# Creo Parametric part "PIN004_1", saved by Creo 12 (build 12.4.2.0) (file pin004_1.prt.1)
Units: Custom; MM, KILOGRAM, SECS

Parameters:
  PTC_WM_ITERATION = "0"
  PTC_WM_VERSION = "-.0"
  PTC_WM_LIFECYCLE_STATE = "In Work"
  PTC_WM_LIFECYCLE = "MO_CADDocument"
  PTC_WM_CREATED_BY = "Maximilian Roepper (Z0017RMS: MO)"
  PTC_WM_CREATED_ON = "18-Sep-26 11:36:42 AM"
  PTC_WM_MODIFIED_BY = "Maximilian Roepper (Z0017RMS: MO)"
  PTC_WM_MODIFIED_ON = "18-Sep-26 11:36:46 AM"
  PDMLINKNUMBER = "PDM000071455347"
  PTC_WM_NAME = "pin004_1.prt"
  PTC_WM_NUMBER = "PDM000071455347"

Other parameters: WEIGHT, WEIGHT_FACTOR, WEIGHT_ADD, _MASS_TEMP, _DIFF_TEMP, MC_ERRORS, SUPPLIER

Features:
  1. coordinate system
  2. datum plane "PRT_YZ"
  3. datum plane "PRT_XY"
  4. datum plane "PRT_XZ"
  5. coordinate system
  6. datum axis
  7. datum axis
  8. datum axis
  9. coordinate system
  10. imported feature

Other named items: PRT, SIEMENS_MO, DRW_VIEW_ORG, PRT_X, PRT_Y, PRT_Z, CS0, ROUGH_GROB

Layers: 00_STD_CSYS-KSYS, 01_STD_PLANES-EBENEN, 02_STD_AXES-ACHSEN, 03_STD_CSYS-KSYS, 24_IMPORT_FEAT-IMPORT_KE

Surfaces: 14 plane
